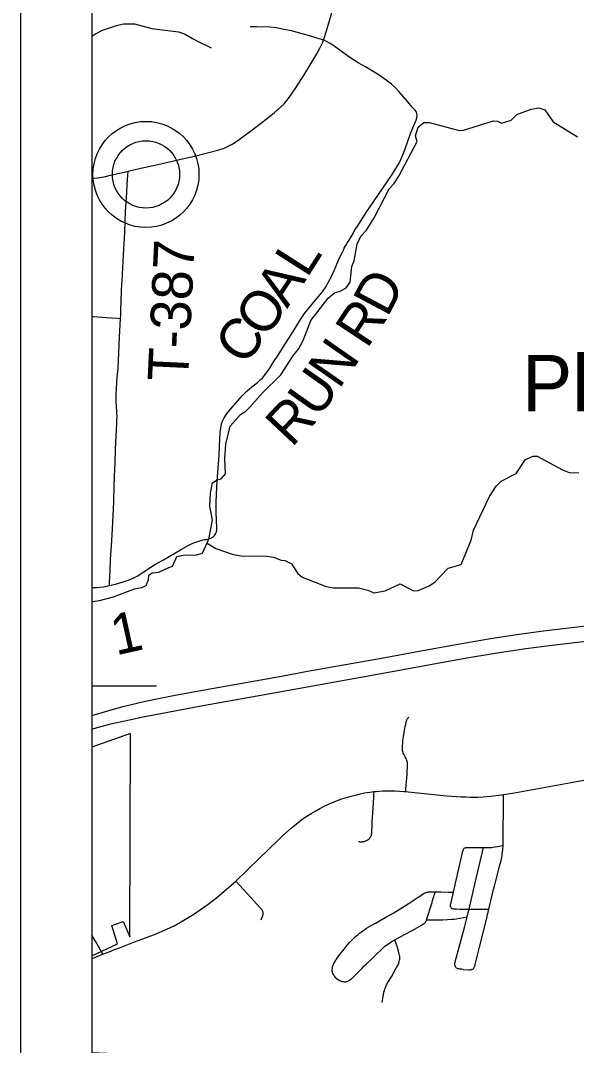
# Model space of a CAD drawing. Extents: x 0 to 34, y 0 to 22.
# Drawn here: x 2 to 2.781, y 15.425 to 16.863 of the extents above; entities that cross this region are included whole.
import ezdxf

# ---------------------------------------------------------------- set-up
doc = ezdxf.new("R2010")
doc.units = 0
for name, color, linetype in [('GM_X_City_Street', 7, 'Continuous'), ('GM_X_County_Road', 7, 'Continuous'), ('GM_X_Interstate_Route', 7, 'Continuous'), ('GM_X_Interstate_Shield', 7, 'Continuous'), ('GM_X_Minor_River', 7, 'Continuous'), ('GM_X_Rail_Line', 7, 'Continuous'), ('GM_X_State_Route', 7, 'Continuous'), ('GM_X_Township_Road', 7, 'Continuous'), ('GM_X_Township_Road_Text', 7, 'Continuous'), ('GM_X_Unincorporated', 7, 'Continuous'), ('GM_X_Unincorporated_Location', 7, 'Continuous'), ('GM_X_Unincorporated_Text', 7, 'Continuous'), ('GM_X_US_Route', 7, 'Continuous'), ('SH_Data', 7, 'Continuous')]:
    doc.layers.add(name, color=color, linetype=linetype)

msp = doc.modelspace()

# ---------------------------------------------------------------- linework, layer by layer
at = {"layer": 'GM_X_City_Street'}
msp.add_lwpolyline([(2.1157, 15.5532), (2.1056, 15.5703), (2.1, 15.5797)], dxfattribs=at)
at = {"layer": 'GM_X_County_Road'}
for points in [[(2.4254, 16.8353), (2.4275, 16.8408), (2.4312, 16.8527), (2.4361, 16.8707), (2.4425, 16.8947), (2.4514, 16.9276), (2.4576, 16.9515), (2.4584, 16.9542)], [(2.1513, 16.6511), (2.1688, 16.6554), (2.193, 16.6609), (2.2112, 16.6651), (2.2293, 16.6692), (2.2443, 16.6725), (2.2624, 16.6768), (2.2773, 16.6808), (2.2861, 16.6838), (2.2918, 16.6864), (2.2972, 16.6893), (2.305, 16.6944), (2.3273, 16.7109), (2.347, 16.7258), (2.3565, 16.7334), (2.3656, 16.7416), (2.37, 16.7458), (2.372, 16.7482), (2.376, 16.753), (2.3816, 16.7605), (2.3868, 16.7682), (2.3983, 16.7866), (2.4063, 16.7997), (2.4159, 16.8157), (2.4204, 16.8239), (2.4243, 16.8322), (2.4254, 16.8353)], [(2.1, 16.6416), (2.1083, 16.6422), (2.1175, 16.6436), (2.1266, 16.6455), (2.1458, 16.6497), (2.1513, 16.6511)]]:
    msp.add_lwpolyline(points, dxfattribs=at)
at = {"layer": 'GM_X_Interstate_Route'}
for points in [[(2.1639, 15.9053), (2.1649, 15.9056), (2.1891, 15.9108), (2.2196, 15.9167), (2.2716, 15.9261), (2.3663, 15.9432), (2.403, 15.9499), (2.507, 15.9685), (2.5651, 15.9792), (2.617, 15.9885), (2.6599, 15.9957), (2.6968, 16.0014), (2.7306, 16.0062), (2.7738, 16.0115), (2.8108, 16.0155)], [(2.6635, 15.9747), (2.6664, 15.9752), (2.7094, 15.9816), (2.7464, 15.9865), (2.8019, 15.993), (2.839, 15.9968), (2.8762, 16), (2.9001, 16.0016), (2.932, 16.0038), (2.9661, 16.0055), (3.0034, 16.0067), (3.0619, 16.0077)], [(2.1716, 15.8858), (2.1894, 15.8894), (2.2535, 15.9014), (2.3636, 15.9211), (2.4859, 15.9431), (2.6265, 15.9686), (2.6635, 15.9747)], [(2.1, 15.8874), (2.1021, 15.8881), (2.1228, 15.8946), (2.1438, 15.9004), (2.1639, 15.9053)], [(2.1, 15.8687), (2.1076, 15.8709), (2.1286, 15.8765), (2.1529, 15.882), (2.1716, 15.8858)]]:
    msp.add_lwpolyline(points, dxfattribs=at)
msp.add_lwpolyline([(2.1, 15.8435), (2.1, 15.5509), (2.1364, 15.5677), (2.1285, 15.5934), (2.1444, 15.5988), (2.1535, 15.5775), (2.1544, 15.8628)], close=True, dxfattribs=at)
at = {"layer": 'GM_X_Interstate_Shield'}
msp.add_line((2.1, 15.9295), (2.1912, 15.9295), dxfattribs=at)
at = {"layer": 'GM_X_Minor_River'}
for points in [[(2.1, 16.8405), (2.1052, 16.844), (2.115, 16.849), (2.1346, 16.8556), (2.1445, 16.8579), (2.16, 16.858), (2.1842, 16.8513), (2.2217, 16.8469), (2.2312, 16.8436), (2.2414, 16.8372), (2.2494, 16.833), (2.2676, 16.8244)], [(2.531, 16.6444), (2.5569, 16.6931), (2.5546, 16.7007), (2.5583, 16.7132), (2.5662, 16.7197), (2.5745, 16.7198), (2.6158, 16.7082), (2.6219, 16.709), (2.6642, 16.7218), (2.6698, 16.7214), (2.6755, 16.7188), (2.6891, 16.7227), (2.697, 16.7307), (2.717, 16.7384), (2.7276, 16.7403), (2.736, 16.7373), (2.7481, 16.7203), (2.7823, 16.6996)], [(2.1, 16.0475), (2.1039, 16.0483), (2.1111, 16.0491), (2.1307, 16.0542), (2.1602, 16.0657), (2.1704, 16.0673), (2.1764, 16.07), (2.1798, 16.0787), (2.1801, 16.0848), (2.185, 16.0879), (2.1941, 16.0887), (2.2085, 16.0952), (2.2134, 16.0975), (2.2197, 16.1108), (2.2311, 16.1132), (2.2454, 16.1129), (2.2556, 16.1156), (2.2646, 16.1354), (2.2694, 16.162), (2.2659, 16.1813), (2.2666, 16.1999), (2.2695, 16.214), (2.2763, 16.2186), (2.2816, 16.2197), (2.288, 16.227), (2.2867, 16.2479), (2.2882, 16.2684), (2.2945, 16.2938), (2.3088, 16.3099), (2.3163, 16.3148), (2.3219, 16.3202), (2.3396, 16.3404), (2.3656, 16.3656), (2.3832, 16.3934), (2.3904, 16.4018), (2.3971, 16.414), (2.4076, 16.4421), (2.432, 16.4734), (2.4407, 16.4806), (2.449, 16.483), (2.4573, 16.4876), (2.4629, 16.4956), (2.4651, 16.5176), (2.4684, 16.5256), (2.4703, 16.5359), (2.4714, 16.5415), (2.4725, 16.5488), (2.4781, 16.5602), (2.4856, 16.5686), (2.4965, 16.5857), (2.5175, 16.6265), (2.5243, 16.6337), (2.531, 16.6444)], [(2.262, 16.1296), (2.2745, 16.1221), (2.2973, 16.1143), (2.3094, 16.1117), (2.3461, 16.1111), (2.3552, 16.11), (2.3662, 16.1059), (2.3711, 16.1052), (2.3806, 16.1007), (2.3893, 16.0871), (2.3954, 16.0818), (2.4291, 16.0687), (2.4397, 16.0668), (2.4745, 16.067), (2.4878, 16.0637), (2.4961, 16.0599), (2.512, 16.0627), (2.5331, 16.0727), (2.5517, 16.0625), (2.5582, 16.0633), (2.5748, 16.0702), (2.5827, 16.0756), (2.5902, 16.0836), (2.6007, 16.0943), (2.6189, 16.0997), (2.6327, 16.1339), (2.636, 16.148), (2.6585, 16.1952), (2.6679, 16.2093), (2.675, 16.2165), (2.6962, 16.2273), (2.7089, 16.2471), (2.7199, 16.2517), (2.7255, 16.2514), (2.7612, 16.2326), (2.7703, 16.2288), (2.7839, 16.2281)]]:
    msp.add_lwpolyline(points, dxfattribs=at)
at = {"layer": 'GM_X_Rail_Line'}
msp.add_lwpolyline([(2.1, 18.4819), (2.1, 15.4153), (3.9123, 15.3323), (3.9451, 15.3313), (3.973, 15.329), (4.0133, 15.3262), (4.0257, 15.3251), (4.0381, 15.324), (4.0782, 15.3206), (4.1061, 15.3185), (4.1743, 15.3141), (4.1849, 15.3132), (4.1956, 15.3121), (4.1973, 15.3118), (5.1044, 15.2759), (5.2458, 15.271), (5.4522, 15.2638), (5.479, 15.731), (5.4821, 15.8189)], dxfattribs=at)
at = {"layer": 'GM_X_State_Route'}
for points in [[(2.6781, 15.7771), (2.6907, 15.7789), (2.773, 15.7937), (2.8522, 15.8086), (2.862, 15.8106), (2.8764, 15.814), (2.8822, 15.8155)], [(2.3022, 15.6556), (2.335, 15.6872), (2.3617, 15.713), (2.3675, 15.7185), (2.3806, 15.7301), (2.3892, 15.7371), (2.3957, 15.7423), (2.4021, 15.7467), (2.4082, 15.7505), (2.4145, 15.7542), (2.4203, 15.7574), (2.4263, 15.7606), (2.4334, 15.7639), (2.4416, 15.7673), (2.4513, 15.7708), (2.4579, 15.7729), (2.4643, 15.7747), (2.4702, 15.7763), (2.4769, 15.7778), (2.4831, 15.7792), (2.4905, 15.7805), (2.4963, 15.7813)], [(2.4963, 15.7813), (2.4993, 15.7813), (2.5083, 15.7821), (2.5144, 15.7823), (2.5194, 15.7822), (2.5258, 15.7821), (2.5383, 15.7814), (2.541, 15.7813)], [(2.541, 15.7813), (2.5444, 15.781), (2.5988, 15.7753), (2.6186, 15.774), (2.6253, 15.7736), (2.6313, 15.7733), (2.6358, 15.7732), (2.6421, 15.7733), (2.6497, 15.7739), (2.6604, 15.7748), (2.6756, 15.7767), (2.6781, 15.7771)], [(2.1157, 15.5532), (2.1164, 15.5535), (2.1244, 15.5566), (2.1318, 15.5595), (2.1388, 15.5622), (2.1599, 15.5703), (2.1706, 15.5741), (2.1817, 15.5782), (2.1882, 15.5807), (2.2056, 15.5882), (2.2156, 15.593), (2.2248, 15.598), (2.2317, 15.602), (2.2432, 15.6092), (2.2541, 15.6165), (2.2635, 15.6232), (2.2727, 15.6301), (2.2787, 15.635), (2.2862, 15.6415), (2.3022, 15.6556)], [(2.1, 15.5467), (2.1071, 15.5497), (2.1157, 15.5532)]]:
    msp.add_lwpolyline(points, dxfattribs=at)
at = {"layer": 'GM_X_Township_Road'}
msp.add_line((2.6298, 15.6162), (2.6578, 15.6164), dxfattribs=at)
for points in [[(2.3223, 16.8543), (2.3314, 16.8541), (2.3499, 16.8536), (2.359, 16.8527), (2.3681, 16.8511), (2.3801, 16.8484), (2.3949, 16.8445), (2.4037, 16.8419), (2.414, 16.839), (2.4254, 16.8353)], [(2.1251, 16.07), (2.1274, 16.0706), (2.131, 16.0715), (2.1336, 16.0722), (2.1362, 16.073), (2.144, 16.0754), (2.1468, 16.0763), (2.1496, 16.0772), (2.1525, 16.0783), (2.1582, 16.0807), (2.1637, 16.0834), (2.1689, 16.0866), (2.1767, 16.0917), (2.1898, 16.1), (2.2006, 16.1062), (2.2167, 16.1157), (2.2249, 16.1203), (2.2355, 16.1264), (2.2382, 16.1278), (2.2411, 16.129), (2.2462, 16.131), (2.2505, 16.1326), (2.255, 16.1339), (2.2585, 16.1345), (2.2618, 16.1349), (2.2646, 16.1356), (2.2673, 16.1366), (2.2699, 16.1381), (2.2722, 16.1402), (2.274, 16.1427), (2.2751, 16.1456), (2.2757, 16.1486), (2.2758, 16.1517), (2.2754, 16.1611), (2.2747, 16.1735), (2.2747, 16.1859), (2.2752, 16.1989), (2.2761, 16.2164), (2.2788, 16.2531), (2.2795, 16.2651), (2.2799, 16.2756), (2.2803, 16.2848), (2.2811, 16.2909), (2.2824, 16.2969), (2.2833, 16.2998), (2.2844, 16.3026), (2.2858, 16.3053), (2.2892, 16.3103), (2.291, 16.3127), (2.2949, 16.3175), (2.305, 16.3293), (2.3112, 16.3362), (2.3176, 16.3428), (2.3249, 16.3488), (2.3323, 16.3545), (2.3362, 16.358), (2.3398, 16.3612), (2.3437, 16.366), (2.3469, 16.3705), (2.3501, 16.3751), (2.3533, 16.3806), (2.3557, 16.3843), (2.3617, 16.3933), (2.3703, 16.4068), (2.3805, 16.4227), (2.3878, 16.435), (2.3932, 16.4434), (2.3989, 16.4516), (2.4095, 16.4646), (2.4183, 16.4754), (2.4239, 16.4822), (2.429, 16.4897), (2.4324, 16.4962), (2.4365, 16.5038), (2.4411, 16.5131), (2.4466, 16.5263), (2.4494, 16.5324), (2.4522, 16.5379), (2.4534, 16.5406), (2.4547, 16.5431), (2.4561, 16.5457), (2.4577, 16.5483), (2.4589, 16.5506), (2.4601, 16.5525), (2.4614, 16.5545), (2.4628, 16.5567), (2.4642, 16.559), (2.4656, 16.5614), (2.4672, 16.5641), (2.4692, 16.5679), (2.4752, 16.5771), (2.4864, 16.5949), (2.4958, 16.6084), (2.5028, 16.6186), (2.5149, 16.6365), (2.5217, 16.6468), (2.5271, 16.655), (2.5316, 16.6626), (2.5346, 16.6686), (2.537, 16.6741), (2.5401, 16.6826), (2.5473, 16.7028), (2.551, 16.7121), (2.5542, 16.7197), (2.5555, 16.723), (2.5564, 16.7263), (2.5568, 16.7296), (2.5564, 16.7321), (2.5556, 16.7348), (2.5538, 16.7374), (2.5498, 16.7413), (2.5437, 16.7484), (2.5318, 16.7624), (2.5254, 16.7692), (2.5209, 16.7734), (2.5134, 16.7791), (2.5034, 16.7858), (2.4952, 16.791), (2.4844, 16.7976), (2.4741, 16.8034), (2.4688, 16.8066), (2.4611, 16.8119), (2.4486, 16.8211), (2.4384, 16.8281), (2.4348, 16.8304), (2.4254, 16.8353)], [(2.1404, 16.4448), (2.1407, 16.4499), (2.1411, 16.4589), (2.1412, 16.4667), (2.1416, 16.4738), (2.1418, 16.4792), (2.1419, 16.4832), (2.142, 16.4864), (2.1421, 16.49), (2.1424, 16.493), (2.1427, 16.4971), (2.1447, 16.5343), (2.1455, 16.5497), (2.1464, 16.5651), (2.1469, 16.581), (2.1475, 16.5952), (2.1492, 16.6208), (2.1499, 16.6332), (2.1509, 16.6455), (2.1513, 16.6511)], [(2.1, 16.4475), (2.1025, 16.4473), (2.1201, 16.4459), (2.1358, 16.4451), (2.1404, 16.4448)], [(2.1251, 16.07), (2.1251, 16.0746), (2.1253, 16.0826), (2.1258, 16.0918), (2.1263, 16.1072), (2.1278, 16.1254), (2.1294, 16.1498), (2.1306, 16.1772), (2.131, 16.1887), (2.1313, 16.1957), (2.1314, 16.2021), (2.1317, 16.21), (2.1322, 16.2236), (2.133, 16.2423), (2.1336, 16.2612), (2.1345, 16.2796), (2.1349, 16.288), (2.1354, 16.2977), (2.1355, 16.3031), (2.1357, 16.3076), (2.1355, 16.3115), (2.1354, 16.316), (2.1349, 16.3202), (2.1344, 16.329), (2.1342, 16.3349), (2.1342, 16.339), (2.1346, 16.3446), (2.1355, 16.3568), (2.137, 16.3751), (2.1391, 16.4184), (2.1404, 16.4448)], [(2.1, 16.0672), (2.1072, 16.0676), (2.1165, 16.0685), (2.1195, 16.069), (2.1225, 16.0695), (2.1251, 16.07)], [(2.541, 15.7813), (2.5412, 15.7847), (2.5416, 15.7907), (2.5423, 15.7999), (2.5427, 15.806), (2.5431, 15.8112), (2.5433, 15.8145), (2.5435, 15.8171), (2.5435, 15.8184), (2.5435, 15.8196), (2.5434, 15.8207), (2.5432, 15.8222), (2.5431, 15.8229), (2.5429, 15.8237), (2.5426, 15.8247), (2.5422, 15.8259), (2.5416, 15.8274), (2.5402, 15.8299), (2.5393, 15.8317), (2.5382, 15.8335), (2.5375, 15.835), (2.5371, 15.8361), (2.5368, 15.8372), (2.5366, 15.8381), (2.5365, 15.8387), (2.5364, 15.8394), (2.5364, 15.842), (2.5365, 15.8453), (2.5367, 15.8492), (2.5369, 15.8523), (2.5372, 15.8552), (2.5376, 15.8581), (2.5387, 15.8642), (2.5397, 15.87), (2.5401, 15.8721), (2.5406, 15.8742), (2.5409, 15.8759), (2.5413, 15.8774), (2.5416, 15.8788), (2.5421, 15.8802), (2.5424, 15.8811), (2.5426, 15.8819), (2.543, 15.8827), (2.5435, 15.8835), (2.5442, 15.8843), (2.5448, 15.8849), (2.5456, 15.8854)], [(2.4746, 15.7111), (2.4759, 15.7109), (2.4769, 15.7108), (2.478, 15.7107), (2.4789, 15.7107), (2.4799, 15.7108), (2.4809, 15.7109), (2.4817, 15.7111), (2.4826, 15.7113), (2.4836, 15.7115), (2.4847, 15.712), (2.4858, 15.7125), (2.4868, 15.7131), (2.4875, 15.7135), (2.4884, 15.7141), (2.4894, 15.7151), (2.4903, 15.716), (2.4911, 15.7171), (2.4917, 15.718), (2.4921, 15.7187), (2.4924, 15.7194), (2.4927, 15.7201), (2.4929, 15.7208), (2.493, 15.7217), (2.4932, 15.7226), (2.4933, 15.7239), (2.4934, 15.7275), (2.4936, 15.7314), (2.4938, 15.7364), (2.494, 15.7398), (2.4943, 15.7445), (2.4947, 15.7517), (2.4956, 15.7643), (2.4961, 15.7749), (2.4963, 15.7813)], [(2.6776, 15.7056), (2.6778, 15.727), (2.6781, 15.7551), (2.6781, 15.7771)], [(2.608, 15.6401), (2.6108, 15.6526), (2.6213, 15.6974), (2.6216, 15.6985), (2.6219, 15.6994), (2.6222, 15.7004), (2.6225, 15.7011), (2.6229, 15.7017), (2.6238, 15.7023)], [(2.6238, 15.7023), (2.6248, 15.7024), (2.6254, 15.7025), (2.6261, 15.7025), (2.6268, 15.7026), (2.6279, 15.7026), (2.6298, 15.7026), (2.6329, 15.7026), (2.6391, 15.7026), (2.6503, 15.7026)], [(2.6298, 15.6162), (2.6379, 15.6511), (2.6503, 15.7026)], [(2.6503, 15.7026), (2.6516, 15.7026), (2.6562, 15.7027), (2.6588, 15.7028), (2.6615, 15.7029), (2.6638, 15.7031), (2.6666, 15.7035), (2.6697, 15.704), (2.6776, 15.7056)], [(2.6578, 15.6164), (2.6629, 15.6379), (2.6642, 15.6438), (2.6659, 15.6504), (2.6672, 15.6559), (2.6736, 15.6796), (2.6748, 15.6845), (2.6754, 15.6868), (2.6759, 15.6893), (2.6762, 15.6908), (2.6765, 15.6933), (2.6767, 15.6957), (2.6772, 15.7), (2.6776, 15.7056)], [(2.3379, 15.6011), (2.3399, 15.6058), (2.3403, 15.6069), (2.3405, 15.6076), (2.3406, 15.6082), (2.3407, 15.609), (2.3407, 15.6098), (2.3407, 15.6108), (2.3406, 15.6118), (2.3403, 15.6128), (2.3399, 15.6137), (2.3393, 15.6146), (2.339, 15.6151), (2.3383, 15.616), (2.3373, 15.6171), (2.3358, 15.6189), (2.3233, 15.6325), (2.3129, 15.6437), (2.3022, 15.6556)], [(2.4433, 15.5195), (2.4422, 15.5206), (2.4412, 15.5218), (2.4406, 15.5226), (2.4402, 15.5233), (2.4395, 15.5244), (2.4387, 15.5262), (2.4383, 15.5271), (2.4381, 15.5281), (2.4378, 15.529), (2.4378, 15.5299), (2.4377, 15.5312), (2.4377, 15.5323), (2.4379, 15.5336), (2.4381, 15.5347), (2.4383, 15.5356), (2.4386, 15.5365), (2.4389, 15.5375), (2.4394, 15.5385), (2.4402, 15.5402), (2.4408, 15.5413), (2.4421, 15.5436), (2.4434, 15.5456), (2.4449, 15.5478), (2.4466, 15.5501), (2.4483, 15.5525), (2.4501, 15.555), (2.4525, 15.558), (2.4558, 15.5622), (2.4587, 15.5657), (2.462, 15.5696), (2.4641, 15.5719), (2.466, 15.5739), (2.4685, 15.5762), (2.4705, 15.5779), (2.4735, 15.5804), (2.4762, 15.5826), (2.4788, 15.5846), (2.4819, 15.5868), (2.4859, 15.5894), (2.4923, 15.5932), (2.4985, 15.5967), (2.5131, 15.6048), (2.5242, 15.6113), (2.5367, 15.6189), (2.5445, 15.6238), (2.5585, 15.6331), (2.5661, 15.638), (2.5671, 15.6386), (2.5678, 15.6389), (2.569, 15.6394), (2.5699, 15.6397), (2.5707, 15.6399), (2.5714, 15.6401), (2.5722, 15.6402), (2.573, 15.6403), (2.5742, 15.6404), (2.5758, 15.6404), (2.5779, 15.6405), (2.5825, 15.6405)], [(2.5702, 15.6013), (2.5779, 15.6258), (2.5787, 15.6285), (2.5796, 15.6314), (2.5805, 15.6342), (2.581, 15.6359), (2.5819, 15.6384), (2.5825, 15.6405)], [(2.5825, 15.6405), (2.5904, 15.6404), (2.6006, 15.6402), (2.608, 15.6401)], [(2.6041, 15.6188), (2.6038, 15.6194), (2.6036, 15.62), (2.6036, 15.6208), (2.6036, 15.6217), (2.6038, 15.6227), (2.6041, 15.6242), (2.6045, 15.6258), (2.608, 15.6401)], [(2.6041, 15.6188), (2.6045, 15.618), (2.6051, 15.6175), (2.6058, 15.6172), (2.6066, 15.617), (2.6077, 15.6168), (2.6093, 15.6167), (2.6124, 15.6165), (2.6168, 15.6164), (2.6298, 15.6162)], [(2.6217, 15.5318), (2.6297, 15.5313), (2.6309, 15.5313), (2.6315, 15.5313), (2.6328, 15.5315), (2.6336, 15.5317), (2.6343, 15.532), (2.6348, 15.5323), (2.6354, 15.5327), (2.6359, 15.5331), (2.6366, 15.5338), (2.6372, 15.5347), (2.6375, 15.5353), (2.638, 15.5365), (2.6383, 15.5376), (2.6386, 15.5386), (2.6391, 15.5407), (2.6447, 15.5631), (2.6543, 15.6019), (2.6578, 15.6164)], [(2.6273, 15.6056), (2.6288, 15.6117), (2.6298, 15.6162)], [(2.5258, 15.5731), (2.5393, 15.5806), (2.551, 15.587), (2.563, 15.5937), (2.5651, 15.595), (2.5665, 15.5959), (2.5674, 15.5966), (2.568, 15.5972), (2.5686, 15.598), (2.5693, 15.5991), (2.5696, 15.5997), (2.57, 15.6005), (2.5702, 15.6013)], [(2.5702, 15.6013), (2.5794, 15.6012), (2.5869, 15.6011), (2.593, 15.6013), (2.5996, 15.6017), (2.6058, 15.6021), (2.6088, 15.6024), (2.6115, 15.6028), (2.6273, 15.6056)], [(2.6217, 15.5318), (2.6196, 15.5319), (2.618, 15.5321), (2.6164, 15.5322), (2.6157, 15.5324), (2.6151, 15.5325), (2.6142, 15.5327), (2.6132, 15.5332), (2.6125, 15.5335), (2.6119, 15.534), (2.6114, 15.5345), (2.6109, 15.5352), (2.6106, 15.5359), (2.6103, 15.5367), (2.6101, 15.5374), (2.6099, 15.5382), (2.6099, 15.539), (2.6099, 15.5398), (2.61, 15.5405), (2.6102, 15.5415), (2.6103, 15.5422), (2.6106, 15.5432), (2.6108, 15.5443), (2.6116, 15.5473), (2.6147, 15.5576), (2.6234, 15.5906), (2.6273, 15.6056)], [(2.4433, 15.5195), (2.4453, 15.5179), (2.4463, 15.5172), (2.4474, 15.5165), (2.448, 15.5162), (2.4488, 15.5158), (2.4495, 15.5155), (2.4503, 15.5152), (2.4511, 15.5149), (2.452, 15.5147), (2.4527, 15.5146), (2.4533, 15.5146), (2.4546, 15.5145), (2.4562, 15.5145), (2.4573, 15.5147), (2.4581, 15.5148), (2.459, 15.5151), (2.4597, 15.5153), (2.4605, 15.5157), (2.4615, 15.5163), (2.4625, 15.517), (2.4651, 15.5192), (2.4685, 15.5222), (2.4738, 15.5275), (2.4798, 15.5336), (2.4822, 15.5361), (2.4852, 15.5391), (2.4873, 15.5411), (2.4923, 15.5456), (2.499, 15.5522), (2.5068, 15.5597), (2.5099, 15.5625), (2.5117, 15.5641), (2.5139, 15.5659), (2.5157, 15.5671), (2.5167, 15.5678), (2.5206, 15.5702), (2.5258, 15.5731)], [(2.5076, 15.4851), (2.5087, 15.4911), (2.5091, 15.4937), (2.5095, 15.4962), (2.5098, 15.4976), (2.5101, 15.4989), (2.5104, 15.5001), (2.5109, 15.5018), (2.5114, 15.5035), (2.5121, 15.5052), (2.5127, 15.5068), (2.5134, 15.5085), (2.514, 15.5099), (2.5148, 15.5114), (2.5155, 15.5129), (2.5166, 15.5146), (2.5198, 15.52), (2.5213, 15.5224), (2.5262, 15.5309), (2.5281, 15.5344), (2.5301, 15.5381), (2.5311, 15.5406), (2.5319, 15.5427), (2.5323, 15.5445), (2.5325, 15.5459), (2.5326, 15.5476), (2.5325, 15.5491), (2.5324, 15.5502), (2.5322, 15.5512), (2.5318, 15.5532), (2.5307, 15.5575), (2.5293, 15.5623), (2.5258, 15.5731)]]:
    msp.add_lwpolyline(points, dxfattribs=at)
at = {"layer": 'GM_X_Unincorporated'}
for radius in [0.0744, 0.0472]:
    msp.add_circle((2.1762, 16.6468), radius, dxfattribs=at)
at = {"layer": 'GM_X_Unincorporated_Location'}
msp.add_line((2.1762, 16.6468), (2.1762, 16.6468), dxfattribs=at)
at = {"layer": 'GM_X_US_Route'}
for points in [[(2.6781, 15.7771), (2.6907, 15.7789), (2.773, 15.7937), (2.8522, 15.8086), (2.862, 15.8106), (2.8764, 15.814), (2.8822, 15.8155)], [(2.3022, 15.6556), (2.335, 15.6872), (2.3617, 15.713), (2.3675, 15.7185), (2.3806, 15.7301), (2.3892, 15.7371), (2.3957, 15.7423), (2.4021, 15.7467), (2.4082, 15.7505), (2.4145, 15.7542), (2.4203, 15.7574), (2.4263, 15.7606), (2.4334, 15.7639), (2.4416, 15.7673), (2.4513, 15.7708), (2.4579, 15.7729), (2.4643, 15.7747), (2.4702, 15.7763), (2.4769, 15.7778), (2.4831, 15.7792), (2.4905, 15.7805), (2.4963, 15.7813)], [(2.4963, 15.7813), (2.4993, 15.7813), (2.5083, 15.7821), (2.5144, 15.7823), (2.5194, 15.7822), (2.5258, 15.7821), (2.5383, 15.7814), (2.541, 15.7813)], [(2.541, 15.7813), (2.5444, 15.781), (2.5988, 15.7753), (2.6186, 15.774), (2.6253, 15.7736), (2.6313, 15.7733), (2.6358, 15.7732), (2.6421, 15.7733), (2.6497, 15.7739), (2.6604, 15.7748), (2.6756, 15.7767), (2.6781, 15.7771)], [(2.1157, 15.5532), (2.1164, 15.5535), (2.1244, 15.5566), (2.1318, 15.5595), (2.1388, 15.5622), (2.1599, 15.5703), (2.1706, 15.5741), (2.1817, 15.5782), (2.1882, 15.5807), (2.2056, 15.5882), (2.2156, 15.593), (2.2248, 15.598), (2.2317, 15.602), (2.2432, 15.6092), (2.2541, 15.6165), (2.2635, 15.6232), (2.2727, 15.6301), (2.2787, 15.635), (2.2862, 15.6415), (2.3022, 15.6556)], [(2.1, 15.5467), (2.1071, 15.5497), (2.1157, 15.5532)]]:
    msp.add_lwpolyline(points, dxfattribs=at)
at = {"layer": 'SH_Data'}
for p, q in [((2, 21), (2, 14)), ((2.1, 20.9), (2.1, 14.1))]:
    msp.add_line(p, q, dxfattribs=at)

# ---------------------------------------------------------------- texts
at = {"layer": 'GM_X_Township_Road_Text'}
for s, height, rotation, p in [('T-387', 0.05682, 87.2771, (2.2352, 16.3555)), ('L', 0.0568, 57.5337, (2.4023, 16.5003)), ('A', 0.0568, 56.7616, (2.3745, 16.4578)), ('D', 0.0568, 62.031, (2.515, 16.445)), ('O', 0.0568, 54.0279, (2.3434, 16.4149)), ('R', 0.0568, 56.6609, (2.4865, 16.4011)), ('C', 0.0568, 52.4533, (2.314, 16.3765)), ('N', 0.0568, 55.1593, (2.447, 16.3444)), ('U', 0.0568, 54.7943, (2.418, 16.3032)), ('R', 0.0568, 46.8052, (2.3807, 16.2626)), ('1', 0.0568, 12.5361, (2.1339, 15.972))]:
    msp.add_text(s, height=height, rotation=rotation, dxfattribs=at).set_placement(p)
at = {"layer": 'GM_X_Unincorporated_Text'}
msp.add_text('Pleasant', height=0.07898, rotation=0, dxfattribs=at).set_placement((2.7042, 16.3145))

doc.saveas('drawing.dxf')
